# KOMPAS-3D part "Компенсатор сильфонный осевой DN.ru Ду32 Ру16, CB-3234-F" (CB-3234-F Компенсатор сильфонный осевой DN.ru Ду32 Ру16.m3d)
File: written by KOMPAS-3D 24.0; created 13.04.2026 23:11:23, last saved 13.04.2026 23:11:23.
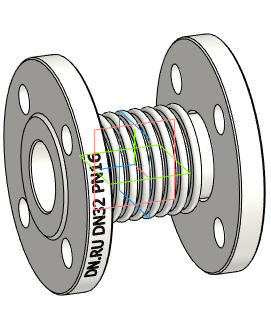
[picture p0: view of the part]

Document properties: Автор: DN.RU; Полное имя файла: D:\PROJECT CAD\DN.RU\...198(ACTUALE). CB-3234-F Компенсатор сильфонный осевой DN.ru\Исходники\DN32\CB-3234-F Компенсатор сильфонный осевой DN.ru Ду32 Ру16.m3d

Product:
- Body: Твердое тело1  | qty 1
    Масса: 3.613942
- Part/product: Компенсатор сильфонный осевой DN.ru Ду32 Ру16  | designation CB-3234-F
    Масса: 3.7
    Раздел спецификации: Прочие изделия
    Комментарий: D140-02111
    Примечание: D140-02111
    additional columns: Типовые

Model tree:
1. Твердое тело1  (labels: Твердое тело1)

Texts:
  CB-3234-F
